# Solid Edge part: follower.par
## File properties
Author: Robert a Rhodes jr
Template: normal.par
Last saved by: Cadcim
Revision: 6
Application: Solid Edge
Accuracy: 0.99
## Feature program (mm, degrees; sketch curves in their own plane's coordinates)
sketch for "unnamed Protrusion 1" plane through (0, 0, 18.8714) normal (0, 0, 1) x-axis (1, 0, 0)
  line (-78.836, 27.8599) -> (-22.3427, 36.4287)
  arc centre (-20.5076, 24.3301) radius 12.2369 from (-22.3427, 36.4287) to (-20.5076, 12.0932) cw
  line (-77.6471, 12.0932) -> (-20.5076, 12.0932)
  arc centre (-77.6471, 20.0214) radius 7.9282 from (-77.6471, 12.0932) to (-78.836, 27.8599) cw
extrude "unnamed Protrusion 1" add finite 8.5604 along +normal
sketch for "ExtrudedProtrusion_2" plane through (0, 0, -11) normal (0, 0, 1) x-axis (1, 0, 0)
  circle centre (-19.7546, 19.6865) radius 3.5
extrude "ExtrudedProtrusion_2" add  Plane_Distance = 11 mm
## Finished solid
Body 1: solid body, 8 faces, 14 edges, 8 vertices.
  Faces by surface: plane 5, cylinder 3
  Edges by curve: line 8, circle 6
Bounding box of the edges (mm): 77.305 x 24.474 x 38.432, from (-85.5752, 12.0932, -11) to (-8.2707, 36.567, 27.4319).
Cylindrical faces by radius (mm): R3.5 x1, R7.9282 x1, R12.2369 x1
Planar faces by outward normal: +z 1, -y 1, -z 2, oblique 1
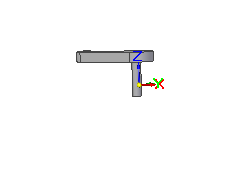
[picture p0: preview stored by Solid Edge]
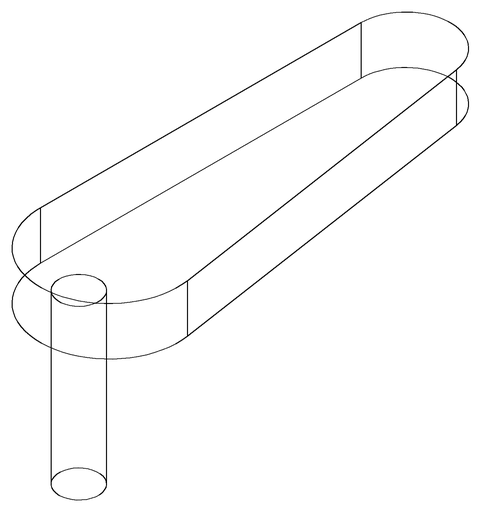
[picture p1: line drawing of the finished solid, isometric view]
